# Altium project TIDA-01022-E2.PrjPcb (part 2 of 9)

## Sheet TIDA-01022-E2_ADC ANALOG INP CH3.SchDoc: ADC12DJxx00_CH3
size 431 x 279 mm; Date: Not shown in title block; ApprovedBy: Not shown in title block; CheckedBy: Not shown in title block; Author: Not shown in title block; CompanyName: Not shown in title block; DrawnBy: Avinash N; Engineer: Not shown in title block; Organization: Not shown in title block; Address1: Not shown in title block; Address2: Not shown in title block; Address3: Not shown in title block; Address4: Not shown in title block; DocumentNumber: 1; Revision: Use project parameter SCH_Rev; SheetNumber: 4; SheetTotal: 26; PageSetup: Record=PageOptions¦CenterHorizontal=True¦CenterVertical=True¦PrintScale=1.00¦XCorrection=1.00¦YCorrection=1.00¦PrintKind=0¦BorderSize=5000000¦LeftOffset=0¦BottomOffset=0¦Orientation=2¦PaperLength=1000¦PaperWidth=1000¦Scale=100¦PaperSource=15¦PrintQuality=600¦MediaType=1¦DitherType=10¦PaperKind=Letter¦PrintScaleMode=1
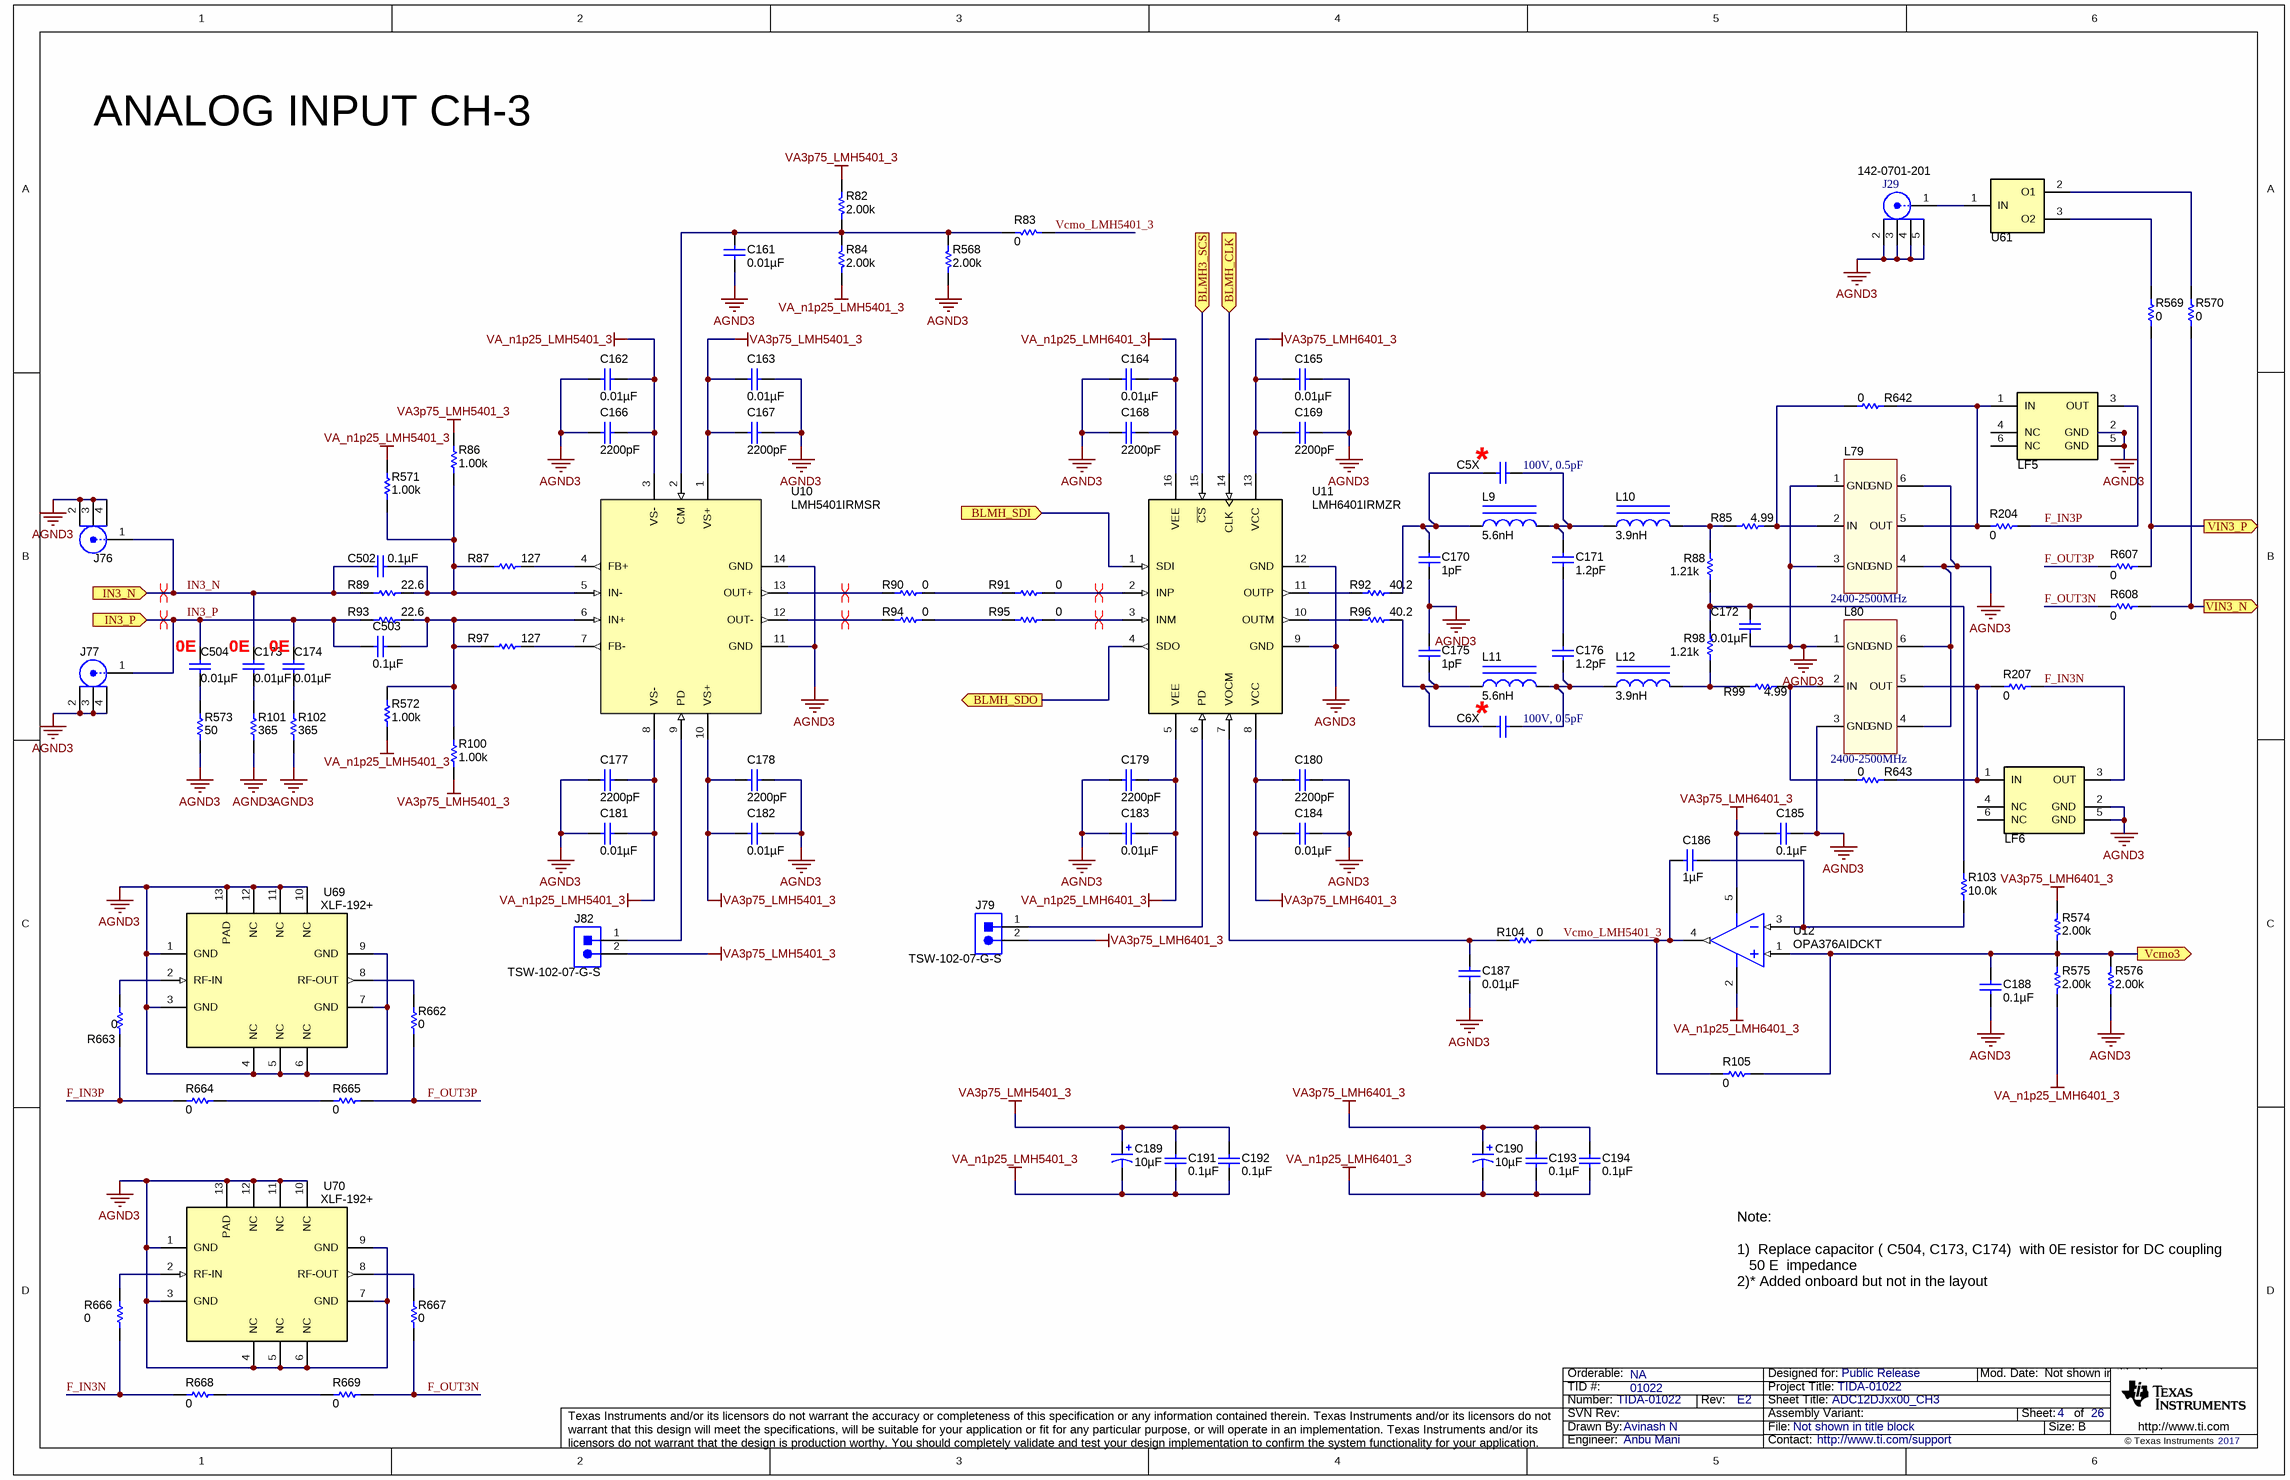
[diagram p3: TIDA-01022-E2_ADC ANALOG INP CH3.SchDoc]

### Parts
C5X  100V, 0.5pF  [0603_1.6x0.8x0.8mm_Reflow Soldering]
C6X  100V, 0.5pF  [0603_1.6x0.8x0.8mm_Reflow Soldering]
C161  ValueDisplayed: 0.01µF  [0402]  (hidden comment: GRM155R71E103KA01D)
C162  ValueDisplayed: 0.01µF  [0306]  (hidden comment: LLL185R71E103MA01L)
C163  ValueDisplayed: 0.01µF  [0306]  (hidden comment: LLL185R71E103MA01L)
C164  ValueDisplayed: 0.01µF  [0306]  (hidden comment: LLL185R71E103MA01L)
C165  ValueDisplayed: 0.01µF  [0306]  (hidden comment: LLL185R71E103MA01L)
C166  ValueDisplayed: 2200pF  [0306]  (hidden comment: LLL185R71H222MA01L)
C167  ValueDisplayed: 2200pF  [0306]  (hidden comment: LLL185R71H222MA01L)
C168  ValueDisplayed: 2200pF  [0306]  (hidden comment: LLL185R71H222MA01L)
C169  ValueDisplayed: 2200pF  [0306]  (hidden comment: LLL185R71H222MA01L)
C170  ValueDisplayed: 1pF  [0402]  (hidden comment: GRM1555C1H1R0CA01D)
C171  ValueDisplayed: 1.2pF  [0402]  (hidden comment: GRM1555C1H1R2BA01D)
C172  ValueDisplayed: 0.01µF  [0402]  (hidden comment: GRM155R71E103KA01D)
C173  ValueDisplayed: 0.01µF  [0402]  (hidden comment: GRM155R71E103KA01D)
C174  ValueDisplayed: 0.01µF  [0402]  (hidden comment: GRM155R71E103KA01D)
C175  ValueDisplayed: 1pF  [0402]  (hidden comment: GRM1555C1H1R0CA01D)
C176  ValueDisplayed: 1.2pF  [0402]  (hidden comment: GRM1555C1H1R2BA01D)
C177  ValueDisplayed: 2200pF  [0306]  (hidden comment: LLL185R71H222MA01L)
C178  ValueDisplayed: 2200pF  [0306]  (hidden comment: LLL185R71H222MA01L)
C179  ValueDisplayed: 2200pF  [0306]  (hidden comment: LLL185R71H222MA01L)
C180  ValueDisplayed: 2200pF  [0306]  (hidden comment: LLL185R71H222MA01L)
C181  ValueDisplayed: 0.01µF  [0306]  (hidden comment: LLL185R71E103MA01L)
C182  ValueDisplayed: 0.01µF  [0306]  (hidden comment: LLL185R71E103MA01L)
C183  ValueDisplayed: 0.01µF  [0306]  (hidden comment: LLL185R71E103MA01L)
C184  ValueDisplayed: 0.01µF  [0306]  (hidden comment: LLL185R71E103MA01L)
C185  ValueDisplayed: 0.1µF  [0402]  (hidden comment: C1005X5R1A104K050BA)
C186  ValueDisplayed: 1µF  [0603]  (hidden comment: C1608X5R1A105K080AC)
C187  ValueDisplayed: 0.01µF  [0402]  (hidden comment: GRM155R71E103KA01D)
C188  ValueDisplayed: 0.1µF  [0402]  (hidden comment: C1005X5R1A104K050BA)
C189  ValueDisplayed: 10µF  [3216-18]  (hidden comment: TPSA106K010R0900)
C190  ValueDisplayed: 10µF  [3216-18]  (hidden comment: TPSA106K010R0900)
C191  ValueDisplayed: 0.1µF  [0402]  (hidden comment: C1005X5R1A104K050BA)
C192  ValueDisplayed: 0.1µF  [0402]  (hidden comment: C1005X5R1A104K050BA)
C193  ValueDisplayed: 0.1µF  [0402]  (hidden comment: C1005X5R1A104K050BA)
C194  ValueDisplayed: 0.1µF  [0402]  (hidden comment: C1005X5R1A104K050BA)
C502  ValueDisplayed: 0.1µF  [0402]  (hidden comment: GRM155R71C104JA88D)
C503  ValueDisplayed: 0.1µF  [0402]  (hidden comment: GRM155R71C104JA88D)
C504  ValueDisplayed: 0.01µF  [0402]  (hidden comment: GRM155R71E103KA01D)
J29  142-0701-201  [Johnson_142-0701-20x]
J76  142-0771-831  [Johnson_142-0771-831]  (value not drawn)
J77  142-0771-831  [Johnson_142-0771-831]  (value not drawn)
J79  TSW-102-07-G-S  [TSW-102-07-G-S]
J82  TSW-102-07-G-S  [TSW-102-07-G-S]
L9  ValueDisplayed: 5.6nH  [LQW18A]  (hidden comment: LQW18AN5N6D10D)
L10  ValueDisplayed: 3.9nH  [0603HC]  (hidden comment: 0603HC-3N9XJLU)
L11  ValueDisplayed: 5.6nH  [LQW18A]  (hidden comment: LQW18AN5N6D10D)
L12  ValueDisplayed: 3.9nH  [0603HC]  (hidden comment: 0603HC-3N9XJLU)
L79  value 2400-2500MHz  [WE-LPF_0603]  (hidden comment: WE-LPF, 748112024)
L80  value 2400-2500MHz  [WE-LPF_0603]  (hidden comment: WE-LPF, 748112024)
LF5  LFL182G45TC3B746  [FIL_LFL18_TC1]  (value not drawn)
LF6  LFL182G45TC3B746  [FIL_LFL18_TC1]  (value not drawn)
R82  ValueDisplayed: 2.00k  [0402]  (hidden comment: CRCW04022K00FKED)
R83  ValueDisplayed: 0  [0402]  (hidden comment: CRCW04020000Z0ED)
R84  ValueDisplayed: 2.00k  [0402]  (hidden comment: CRCW04022K00FKED)
R85  ValueDisplayed: 4.99  [0402]  (hidden comment: CRCW04024R99FKED)
R86  ValueDisplayed: 1.00k  [0402]  (hidden comment: ERJ-2RKF1001X)
R87  ValueDisplayed: 127  [0402]  (hidden comment: CRCW0402127RFKED)
R88  ValueDisplayed: 1.21k  [0402]  (hidden comment: CRCW04021K21FKED)
R89  ValueDisplayed: 22.6  [0402]  (hidden comment: CRCW040222R6FKED)
R90  ValueDisplayed: 0  [0402]  (hidden comment: CRCW04020000Z0ED)
R91  ValueDisplayed: 0  [0402]  (hidden comment: CRCW04020000Z0ED)
R92  ValueDisplayed: 40.2  [0402]  (hidden comment: CRCW040240R2FKED)
R93  ValueDisplayed: 22.6  [0402]  (hidden comment: CRCW040222R6FKED)
R94  ValueDisplayed: 0  [0402]  (hidden comment: CRCW04020000Z0ED)
R95  ValueDisplayed: 0  [0402]  (hidden comment: CRCW04020000Z0ED)
R96  ValueDisplayed: 40.2  [0402]  (hidden comment: CRCW040240R2FKED)
R97  ValueDisplayed: 127  [0402]  (hidden comment: CRCW0402127RFKED)
R98  ValueDisplayed: 1.21k  [0402]  (hidden comment: CRCW04021K21FKED)
R99  ValueDisplayed: 4.99  [0402]  (hidden comment: CRCW04024R99FKED)
R100  ValueDisplayed: 1.00k  [0402]  (hidden comment: ERJ-2RKF1001X)
R101  ValueDisplayed: 365  [0402]  (hidden comment: CRCW0402365RFKED)
R102  ValueDisplayed: 365  [0402]  (hidden comment: CRCW0402365RFKED)
R103  ValueDisplayed: 10.0k  [0402]  (hidden comment: CRCW040210K0FKED)
R104  ValueDisplayed: 0  [0402]  (hidden comment: CRCW04020000Z0ED)
R105  ValueDisplayed: 0  [0402]  (hidden comment: CRCW04020000Z0ED)
R204  ValueDisplayed: 0  [0402_FILTER]  (hidden comment: CRCW04020000Z0ED)
R207  ValueDisplayed: 0  [0402_FILTER]  (hidden comment: CRCW04020000Z0ED)
R568  ValueDisplayed: 2.00k  [0402]  (hidden comment: CRCW04022K00FKED)
R569  ValueDisplayed: 0  [0201_adc]  (hidden comment: CRCW02010000Z0ED)
R570  ValueDisplayed: 0  [0201_adc]  (hidden comment: CRCW02010000Z0ED)
R571  ValueDisplayed: 1.00k  [0402]  (hidden comment: ERJ-2RKF1001X)
R572  ValueDisplayed: 1.00k  [0402]  (hidden comment: ERJ-2RKF1001X)
R573  ValueDisplayed: 50  [0402]  (hidden comment: FC0402E50R0BTBST1)
R574  ValueDisplayed: 2.00k  [0402]  (hidden comment: CRCW04022K00FKED)
R575  ValueDisplayed: 2.00k  [0402]  (hidden comment: CRCW04022K00FKED)
R576  ValueDisplayed: 2.00k  [0402]  (hidden comment: CRCW04022K00FKED)
R607  ValueDisplayed: 0  [0201_adc]  (hidden comment: CRCW02010000Z0ED)
R608  ValueDisplayed: 0  [0201_adc]  (hidden comment: CRCW02010000Z0ED)
R642  ValueDisplayed: 0  [0402_FILTER]  (hidden comment: CRCW04020000Z0ED)
R643  ValueDisplayed: 0  [0402_FILTER]  (hidden comment: CRCW04020000Z0ED)
R662  ValueDisplayed: 0  [0201_adc]  (hidden comment: CRCW02010000Z0ED)
R663  ValueDisplayed: 0  [0201_adc]  (hidden comment: CRCW02010000Z0ED)
R664  ValueDisplayed: 0  [0201_adc]  (hidden comment: CRCW02010000Z0ED)
R665  ValueDisplayed: 0  [0201_adc]  (hidden comment: CRCW02010000Z0ED)
R666  ValueDisplayed: 0  [0201_adc]  (hidden comment: CRCW02010000Z0ED)
R667  ValueDisplayed: 0  [0201_adc]  (hidden comment: CRCW02010000Z0ED)
R668  ValueDisplayed: 0  [0201_adc]  (hidden comment: CRCW02010000Z0ED)
R669  ValueDisplayed: 0  [0201_adc]  (hidden comment: CRCW02010000Z0ED)
U10  LMH5401IRMSR  [RMS0014A]
U11  LMH6401IRMZR  [RMZ0016A]
U12  OPA376AIDCKT  [DCK0005A_N]
U61  BAL-0006SMG  [Marki_BAL-0006SMG]  (value not drawn)
U69  XLF-192+  [DQ1225]
U70  XLF-192+  [DQ1225]

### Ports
BLMH3_SCS (in), BLMH_CLK (in), BLMH_SDI (in), BLMH_SDO (out), IN3_N (in), IN3_P (in), Vcmo3 (out), VIN3_N (out), VIN3_P (out)

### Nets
AGND3: C161.2 C162.1 C163.1 C164.1 C165.1 C166.2 C167.2 C168.2 C169.2 C170.2 C172.2 C175.2 C177.2 C178.2 C179.2 C180.2 C181.1 C182.1 C183.1 C184.1 C185.1 C187.2 C188.2 J29.2 J29.3 J29.4 J29.5 J76.2 J76.3 J76.4 J77.2 J77.3 J77.4 L79.1(GND) L79.3(GND) L79.4(GND) L79.6(GND) L80.1(GND) L80.3(GND) L80.4(GND) L80.6(GND) LF5.2(GND) LF5.5(GND) LF6.2(GND) LF6.5(GND) R101.1 R102.1 R568.1 R573.1 R576.1 U10.11(GND) U10.14(GND) U11.9(GND) U11.12(GND) U69.1(GND) U69.3(GND) U69.4(NC) U69.5(NC) U69.6(NC) U69.7(GND) U69.9(GND) U69.10(NC) U69.11(NC) U69.12(NC) U69.13(PAD) U70.1(GND) U70.3(GND) U70.4(NC) U70.5(NC) U70.6(NC) U70.7(GND) U70.9(GND) U70.10(NC) U70.11(NC) U70.12(NC) U70.13(PAD)  [project net AGND]
VA3p75_LMH5401_3: C163.2 C167.1 C178.1 C182.2 C189.1(+) C191.1 C192.1 J82.2 R82.2 R86.2 R100.1 U10.1(VS+) U10.10(VS+)
VA3p75_LMH6401_3: C165.2 C169.1 C180.1 C184.2 C185.2 C190.1(+) C193.1 C194.1 J79.2 R574.2 U11.8(VCC) U11.13(VCC) U12.5(V+)
VA_n1p25_LMH5401_3: C162.2 C166.1 C177.1 C181.2 C189.2(-) C191.2 C192.2 R84.1 R571.2 R572.2 U10.3(VS-) U10.8(VS-)
VA_n1p25_LMH6401_3: C164.2 C168.1 C179.1 C183.2 C190.2(-) C193.2 C194.2 R575.1 U11.5(VEE) U11.16(VEE) U12.2(V-)
BLMH3_SCS: U11.15(~{CS}) ; port BLMH3_SCS
BLMH_CLK: U11.14(CLK) ; port BLMH_CLK
BLMH_SDI: U11.1(SDI) ; port BLMH_SDI
BLMH_SDO: U11.4(SDO) ; port BLMH_SDO
F_IN3N: LF6.3(OUT) R207.2 R666.1 R668.1
F_IN3P: LF5.3(OUT) R204.2 R663.1 R664.1
F_OUT3N: R608.1 R667.1 R669.2
F_OUT3P: R607.1 R662.1 R665.2
IN3_N: C173.1 C502.2 J76.1 R89.1 ; port IN3_N
IN3_P: C174.1 C503.1 C504.1 J77.1 R93.1 ; port IN3_P
Vcmo3: C188.1 R105.1 R574.1 R575.2 R576.2 U12.1(IN+) ; port Vcmo3
Vcmo_LMH5401_3: C186.1 R83.2 R104.1 R105.2 U12.4(OUT)
VIN3_N: R570.2 R608.2 ; port VIN3_N
VIN3_P: R569.2 R607.2 ; port VIN3_P
NetC5X_1: C5X.1 C170.1 L9.1 R92.1
NetC5X_2: C5X.2 C171.1 L9.2 L10.1
NetC6X_1: C6X.1 C175.1 L11.1 R96.1
NetC6X_2: C6X.2 C176.1 L11.2 L12.1
NetC161_1: C161.1 R82.1 R83.1 R84.2 R568.2 U10.2(CM)
NetC171_2: C171.2 C176.2
NetC172_1: C172.1 R88.1 R98.1 R103.2
NetC173_2: C173.2 R101.2
NetC174_2: C174.2 R102.2
NetC186_2: C186.2 R103.1 U12.3(IN-)
NetC187_1: C187.1 R104.2 U11.7(VOCM)
NetC502_1: C502.1 R86.1 R87.1 R89.2 R571.1 U10.5(IN-)
NetC503_2: C503.2 R93.2 R97.1 R100.2 R572.1 U10.6(IN+)
NetC504_2: C504.2 R573.2
NetJ29_1: J29.1 U61.1(IN)
NetJ79_1: J79.1 U11.6(PD)
NetJ82_1: J82.1 U10.9(PD)
NetL10_2: L10.2 R85.1 R88.2
NetL12_2: L12.2 R98.2 R99.1
NetL79_2: L79.2(IN) R85.2 R642.1
NetL79_5: L79.5(OUT) LF5.1(IN) R204.1 R642.2
NetL80_2: L80.2(IN) R99.2 R643.1
NetL80_5: L80.5(OUT) LF6.1(IN) R207.1 R643.2
NetR87_2: R87.2 U10.4(FB+)
NetR90_1: R90.1 U10.13(OUT+)
NetR90_2: R90.2 R91.2
NetR91_1: R91.1 U11.2(INP)
NetR92_2: R92.2 U11.11(OUTP)
NetR94_1: R94.1 U10.12(OUT-)
NetR94_2: R94.2 R95.2
NetR95_1: R95.1 U11.3(INM)
NetR96_2: R96.2 U11.10(OUTM)
NetR97_2: R97.2 U10.7(FB-)
NetR569_1: R569.1 U61.3(O2)
NetR570_1: R570.1 U61.2(O1)
NetR662_2: R662.2 U69.8(RF-OUT)
NetR663_2: R663.2 U69.2(RF-IN)
NetR664_2: R664.2 R665.1
NetR666_2: R666.2 U70.2(RF-IN)
NetR667_2: R667.2 U70.8(RF-OUT)
NetR668_2: R668.2 R669.1

Not connected (* = marked no-connect by the designer): LF5 4(NC) 6(NC); LF6 4(NC) 6(NC)

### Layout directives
differential pair: IN3_N, IN3_P, NetR90_1, NetR91_1, NetR94_1, NetR95_1

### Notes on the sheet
- ANALOG INPUT CH-3
- (near C5X) *
- (near C504) 0E
- (near C173) 0E
- (near C174) 0E
- *
- Note:
  1)  Replace capacitor ( C504, C173, C174)  with 0E resistor for DC coupling
  50 E  impedance
  2)* Added onboard but not in the layout

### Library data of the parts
C5X C6X = 885012006086: WCAP-CSGP Ceramic Capacitors, 0603, NP0, 100V, 0.5pF; Rated Voltage: 100V DC
C161 C172-C174 C187 C504 = GRM155R71E103KA01D: CAP, CERM, 0.01 µF, 25 V, +/- 10%, X7R, 0402; Manufacturer: MuRata; Polarized: N; CompType: Capacitor; Value: 0.01uF; U/M: EA; Cap_F: 0.00000001; Tolerance_%: 10; Value1: Unknown; VDC_V: 25; Value2: 25V; TaMin_C: -55; TaMax_C: 125; SizeArea_mm2: 0.5; SizeAreaWB_mm2: 3; SizeX_mm: 1; SizeZ_mm: 0.6; AEC Category: Q200
C162-C165 C181-C184 = LLL185R71E103MA01L: CAP, CERM, 0.01 µF, 25 V, +/- 20%, X7R, 0306; Manufacturer: MuRata; Polarized: N; CompType: Capacitor; Value: 0.01uF; U/M: EA; Cap_F: 0.00000001; Tolerance_%: 20; Value1: Unknown; VDC_V: 25; Value2: 25V; TaMin_C: -55; TaMax_C: 125; SizeArea_mm2: 1.28; SizeAreaWB_mm2: 4.68; SizeX_mm: 0.8; SizeY_mm: 1.6; SizeZ_mm: 0.6; AEC Category: Q200
C166-C169 C177-C180 = LLL185R71H222MA01L: CAP, CERM, 2200 pF, 50 V, +/- 20%, X7R, 0306; Manufacturer: MuRata; Polarized: N; CompType: Capacitor; Value: 2200pF; U/M: EA; Cap_F: 0.0000000022; Tolerance_%: 20; Value1: Unknown; VDC_V: 50; Value2: 50V; TaMin_C: -55; TaMax_C: 125; SizeArea_mm2: 1.28; SizeAreaWB_mm2: 4.68; SizeX_mm: 0.8; SizeY_mm: 1.6; SizeZ_mm: 0.6; AEC Category: Q200
C170 C175 = GRM1555C1H1R0CA01D: CAP, CERM, 1 pF, 50 V, +/- 5%, C0G/NP0, 0402; Manufacturer: MuRata; Polarized: N; CompType: Capacitor; Value: 1pF; U/M: EA; Cap_F: 0.000000000001; Tolerance_%: 5; Value1: Unknown; VDC_V: 50; Value2: 50V; TaMin_C: -55; TaMax_C: 125; SizeArea_mm2: 0.5; SizeAreaWB_mm2: 3; SizeX_mm: 1; SizeZ_mm: 0.6; AEC Category: Q200
C171 C176 = GRM1555C1H1R2BA01D: CAP, CERM, 1.2 pF, 50 V, +/- 8.3%, C0G/NP0, 0402; Manufacturer: MuRata; Polarized: N; CompType: Capacitor; Value: 1.2pF; U/M: EA; Cap_F: 0.0000000000012; Tolerance_%: 8.3; Value1: Unknown; VDC_V: 50; Value2: 50V; TaMin_C: -55; TaMax_C: 125; SizeArea_mm2: 0.5; SizeAreaWB_mm2: 3; SizeX_mm: 1; SizeZ_mm: 0.6; AEC Category: Q200
C185 C188 C191-C194 = C1005X5R1A104K050BA: CAP, CERM, 0.1 µF, 10 V, +/- 10%, X5R, 0402; Manufacturer: TDK; Polarized: N; CompType: Capacitor; Value: 0.1uF; U/M: EA; Cap_F: 0.0000001; Tolerance_%: 10; Value1: Unknown; Value2: 10V; TaMin_C: -55; TaMax_C: 85; SizeArea_mm2: 0.5; SizeAreaWB_mm2: 3; SizeX_mm: 1; SizeZ_mm: 0.6; AEC Category: Q200
C186 = C1608X5R1A105K080AC: CAP, CERM, 1 µF, 10 V, +/- 10%, X5R, 0603; Manufacturer: TDK; Polarized: N; CompType: Capacitor; Value: 1uF; U/M: EA; Cap_F: 0.000001; Tolerance_%: 10; Value1: Unknown; Value2: 10V; TaMin_C: -55; TaMax_C: 85; SizeArea_mm2: 1.28; SizeAreaWB_mm2: 4.68; SizeX_mm: 1.6; SizeY_mm: 0.8; SizeZ_mm: 1; AEC Category: Q200
C189 C190 = TPSA106K010R0900: CAP, TA, 10 µF, 10 V, +/- 10%, 0.9 ohm, SMD; Manufacturer: AVX; Polarized: Y; CompType: Capacitor; Value: 10uF; U/M: EA; Cap_F: 0.00001; Tolerance_%: 10; Value1: 0.9 ohm; Value2: 10V; ESR_ohm: 0.9; IRMS_A: 0.26; TaMin_C: -55; TaMax_C: 125; Cap_Case: A; SizeAreaWB_mm2: 10.92; SizeArea_mm2: 5.12; SizeX_mm: 3.2; SizeY_mm: 1.6; SizeZ_mm: 1.8; AEC Category: Q200
C502 C503 = GRM155R71C104JA88D: CAP, CERM, 0.1 µF, 16 V, +/- 5%, X7R, 0402; Manufacturer: MuRata; Polarized: N; CompType: Capacitor; Value: 0.1uF; U/M: EA; Cap_F: 0.0000001; Tolerance_%: 5; Value1: Unknown; VDC_V: 16; Value2: 16V; TaMin_C: -55; TaMax_C: 125; SizeArea_mm2: 0.5; SizeAreaWB_mm2: 3; SizeX_mm: 1; SizeZ_mm: 0.6; AEC Category: Q200
J29 = 142-0701-201: Connector, TH, SMA; Manufacturer: Emerson Network Power; SymbolCreator: X0208326
J76 J77 = 142-0771-831: JACK, SMA, 50 Ohm, Gold, Edge Mount; Manufacturer: Johnson; SymbolCreator: Altium; Gender: Female; Voltage_V: 170
J79 J82 = TSW-102-07-G-S: Header, 100mil, 2x1, Gold, TH; Manufacturer: Samtec; SymbolCreator: a0412235; Pitch_mm: 2.54; Gender: Male; Shrouded: N; Row_Count: 1; Current_A: 6.3; Voltage_V: 550; Cert_CSA: Y
L9 L11 = LQW18AN5N6D10D: Inductor, Wirewound, 5.6 nH, 0.9 A, 0.045 ohm, SMD; Manufacturer: MuRata; Value: 5.6nH; Ind_H: 5.6E-9; Imax_A: 0.9; Irms: 0.9A @ C rise; DCR_ohm: 0.045; Value2: 0.9A; SizeAreaWB_mm2: 4.68; SizeArea_mm2: 1.28; SizeX_mm: 1.6; SizeY_mm: 0.8; SizeZ_mm: 1; AEC Category: Q200; AEC Qualified: N
L10 L12 = 0603HC-3N9XJLU: Inductor, Wirewound, Ceramic, 3.9 nH, 2.2 A, 0.054 ohm, SMD; Manufacturer: Coilcraft; Value: 3.9nH; Ind_H: 3.9E-9; Imax_A: 2.2; Irms: 2.4A @ 20C rise; DCR_ohm: 0.054; Value2: 2.2A; SizeAreaWB_mm2: 5.936; SizeArea_mm2: 2.016; SizeX_mm: 1.8; SizeY_mm: 1.12; SizeZ_mm: 1.02; AEC Category: Q200
L79 L80 = WE-LPF, 748112024: WE-LPF Multilayer Chip Low-Pass Filter, size 0603, 2400-2500MHz
LF5 LF6 = LFL182G45TC3B746: Filter for Communication Equipment, SMD; Manufacturer: MuRata; SymbolCreator: Altium; SizeAreaWB_mm2: 4.68; SizeArea_mm2: 1.28; SizeX_mm: 1.6; SizeY_mm: 0.8; SizeZ_mm: 0.7
R82 R84 R568 R574-R576 = CRCW04022K00FKED: RES, 2.00 k, 1%, 0.063 W, 0402; Manufacturer: Vishay-Dale; CompType: Resistor; Value: 2.00k; Res_ohm: 2000; Value_Code: 2k00; Tolerance_%: 1; Power_W: 0.063; Value2: 0.063W; VDC_V: 50; TempCo: 100 ppm/C; SizeArea_mm2: 0.5; SizeZ_mm: 0.6; EIA_Code: E96; U/M: EA; AEC Category: Q200
R83 R90 R91 R94 R95 R104 R105 R204 R207 R642 R643 = CRCW04020000Z0ED: RES, 0, 5%, 0.063 W, 0402; Manufacturer: Vishay-Dale; CompType: Resistor; Value: 0; Value_Code: 0000; Tolerance_%: 5; Power_W: 0.063; Value2: 0.063W; VDC_V: 50; TempCo: 200 ppm/C; SizeArea_mm2: 0.5; SizeX_mm: 1; SizeZ_mm: 0.6; EIA_Code: E24; U/M: EA; AEC Category: Q200
R85 R99 = CRCW04024R99FKED: RES, 4.99, 1%, 0.063 W, 0402; Manufacturer: Vishay-Dale; CompType: Resistor; Value: 4.99; Value_Code: 4R99; Tolerance_%: 1; Power_W: 0.063; Value2: 0.063W; VDC_V: 50; TempCo: 100 ppm/C; SizeArea_mm2: 0.5; SizeZ_mm: 0.6; EIA_Code: E96; U/M: EA; AEC Category: Q200
R86 R100 R571 R572 = ERJ-2RKF1001X: RES, 1.00 k, 1%, 0.1 W, 0402; Manufacturer: Panasonic; CompType: Resistor; Value: 1.00k; Res_ohm: 1000; Value_Code: 1k00; Tolerance_%: 1; Power_W: 0.1; Value2: 0.1W; VDC_V: 50; TempCo: 100 ppm/C; SizeArea_mm2: 0.5; SizeZ_mm: 0.6; EIA_Code: E96; U/M: EA; AEC Category: Q200
R87 R97 = CRCW0402127RFKED: RES, 127, 1%, 0.063 W, 0402; Manufacturer: Vishay-Dale; CompType: Resistor; Value: 127; Value_Code: 127R; Tolerance_%: 1; Power_W: 0.063; Value2: 0.063W; VDC_V: 50; TempCo: 100 ppm/C; SizeArea_mm2: 0.5; SizeZ_mm: 0.6; EIA_Code: E96; U/M: EA; AEC Category: Q200
R88 R98 = CRCW04021K21FKED: RES, 1.21 k, 1%, 0.063 W, 0402; Manufacturer: Vishay-Dale; CompType: Resistor; Value: 1.21k; Res_ohm: 1210; Value_Code: 1k21; Tolerance_%: 1; Power_W: 0.063; Value2: 0.063W; VDC_V: 50; TempCo: 100 ppm/C; SizeArea_mm2: 0.5; SizeZ_mm: 0.6; EIA_Code: E96; U/M: EA; AEC Category: Q200
R89 R93 = CRCW040222R6FKED: RES, 22.6, 1%, 0.063 W, 0402; Manufacturer: Vishay-Dale; CompType: Resistor; Value: 22.6; Value_Code: 22R6; Tolerance_%: 1; Power_W: 0.063; Value2: 0.063W; VDC_V: 50; TempCo: 100 ppm/C; SizeArea_mm2: 0.5; SizeZ_mm: 0.6; EIA_Code: E96; U/M: EA; AEC Category: Q200
R92 R96 = CRCW040240R2FKED: RES, 40.2, 1%, 0.063 W, 0402; Manufacturer: Vishay-Dale; CompType: Resistor; Value: 40.2; Value_Code: 40R2; Tolerance_%: 1; Power_W: 0.063; Value2: 0.063W; VDC_V: 50; TempCo: 100 ppm/C; SizeArea_mm2: 0.5; SizeZ_mm: 0.6; EIA_Code: E96; U/M: EA; AEC Category: Q200
R101 R102 = CRCW0402365RFKED: RES, 365, 1%, 0.063 W, 0402; Manufacturer: Vishay-Dale; CompType: Resistor; Value: 365; Value_Code: 365R; Tolerance_%: 1; Power_W: 0.063; Value2: 0.063W; VDC_V: 50; TempCo: 100 ppm/C; SizeArea_mm2: 0.5; SizeZ_mm: 0.6; EIA_Code: E96; U/M: EA; AEC Category: Q200
R103 = CRCW040210K0FKED: RES, 10.0 k, 1%, 0.063 W, 0402; Manufacturer: Vishay-Dale; CompType: Resistor; Value: 10.0k; Res_ohm: 10000; Value_Code: 10k0; Tolerance_%: 1; Power_W: 0.063; Value2: 0.063W; VDC_V: 50; TempCo: 100 ppm/C; SizeArea_mm2: 0.5; SizeZ_mm: 0.6; EIA_Code: E96; U/M: EA; AEC Category: Q200
R569 R570 R607 R608 R662-R669 = CRCW02010000Z0ED: RES, 0, 5%, 0.05 W, 0201; Manufacturer: Vishay-Dale; CompType: Resistor; Value: 0; Value_Code: 0000; Tolerance_%: 5; Power_W: 0.05; Value2: 0.05W; TempCo: ppm/C; SizeArea_mm2: 0.18; SizeX_mm: 0.6; SizeY_mm: 0.3; SizeZ_mm: 0.26; EIA_Code: E24; U/M: EA; AEC Category: Q200; AEC Qualified: N
R573 = FC0402E50R0BTBST1: RES, 50, 0.1%, 0.5 W, 0402; Manufacturer: Vishay Thin Film; CompType: Resistor; Value: 50; Value_Code: 50R0; Tolerance_%: 0.1; Power_W: 0.5; Value2: 0.5W; TempCo: 0.1 ppm/C; SizeX_mm: 1; SizeZ_mm: 0.6; U/M: EA; AEC Category: Q200; AEC Qualified: N
U10 = LMH5401IRMSR: 8GHz Ultra Wideband Fully Differential Amplifier, RMS0014A (UQFN-14); Alternate PartNumber: LMH5401IRMST; Manufacturer: Texas Instruments; SymbolCreator: Altium; SizeArea_mm2: 6.25; SizeAreaWB_mm2: 12.25; SizeX_mm: 2.5; SizeZ_mm: 0.6; CompType: IC; U/M: EA
U11 = LMH6401IRMZR: 4.5 GHz Ultra Wideband Digital Variable Gain Amplifier, RMZ0016A (UQFN-HR-16); Alternate PartNumber: LMH6401IRMZT; Manufacturer: Texas Instruments; SymbolCreator: Altium; SizeArea_mm2: 9; SizeAreaWB_mm2: 16; SizeX_mm: 3; SizeZ_mm: 0.65; CompType: IC; U/M: EA
U12 = OPA376AIDCKT: Precision, Low Noise, Low Iq Operational Amplifier, 2.2 to 5.5 V, -40 to 125 degC, 5-pin SOT23 (DCK0005A), Green (RoHS & no Sb/Br); Manufacturer: Texas Instruments; Alternate PartNumber: Equivalent; CMRR(Min)(dB): 76; IIB(Max)(pA): 10; Iq per channel(Max)(mA): 0.95; Number of Channels: 1; Offset Drift(Typ)(uV/C): 0.32; Slew Rate(Typ)(V/us): 2; Sub Family: Low Input Bias Current Amp (<=10pA), Low Noise Amp (<=10nV/rtHz), Low Offset Voltage Amplifier (<=500uV), Low Supply Voltage Amplifier (<=2.7V), Precision Amplifier; Total Supply Voltage(Max)(+5V is 5, +/-5V is 10): 5.5; Total Supply Voltage(Min)(+5V is 5, +/-5V is 10): 2.2; Vio (25C)(Max)(mV): 0.025; Vn at 1kHz(Typ)(nV/rtHz): 7.5
U61 = BAL-0006SMG: Broadband Balun, 500 kHz to 6 GHz; Manufacturer: Marki Microwave; SymbolCreator: Altium; SizeAreaWB_mm2: 102.6169; SizeArea_mm2: 66.0969; SizeX_mm: 8.13; SizeZ_mm: 3.94
U69 U70 = CMP-0077784-1: Reflectionless Low Pass Filter, SMD; Manufacturer: Minicircuits; SizeArea_mm2: 9; SizeAreaWB_mm2: 16; SizeY_mm: 3; SizeZ_mm: 0.89

## Sheet TIDA-01022-E2_ADC ANALOG INP CH4.SchDoc: ADC12DJxx00_CH4
size 431 x 279 mm; Date: Not shown in title block; ApprovedBy: Not shown in title block; CheckedBy: Not shown in title block; Author: Not shown in title block; CompanyName: Not shown in title block; DrawnBy: Avinash N; Engineer: Not shown in title block; Organization: Not shown in title block; Address1: Not shown in title block; Address2: Not shown in title block; Address3: Not shown in title block; Address4: Not shown in title block; DocumentNumber: 1; Revision: Use project parameter SCH_Rev; SheetNumber: 5; SheetTotal: 26; PageSetup: Record=PageOptions¦CenterHorizontal=True¦CenterVertical=True¦PrintScale=1.00¦XCorrection=1.00¦YCorrection=1.00¦PrintKind=0¦BorderSize=5000000¦LeftOffset=0¦BottomOffset=0¦Orientation=2¦PaperLength=1000¦PaperWidth=1000¦Scale=100¦PaperSource=15¦PrintQuality=600¦MediaType=1¦DitherType=10¦PaperKind=Letter¦PrintScaleMode=1
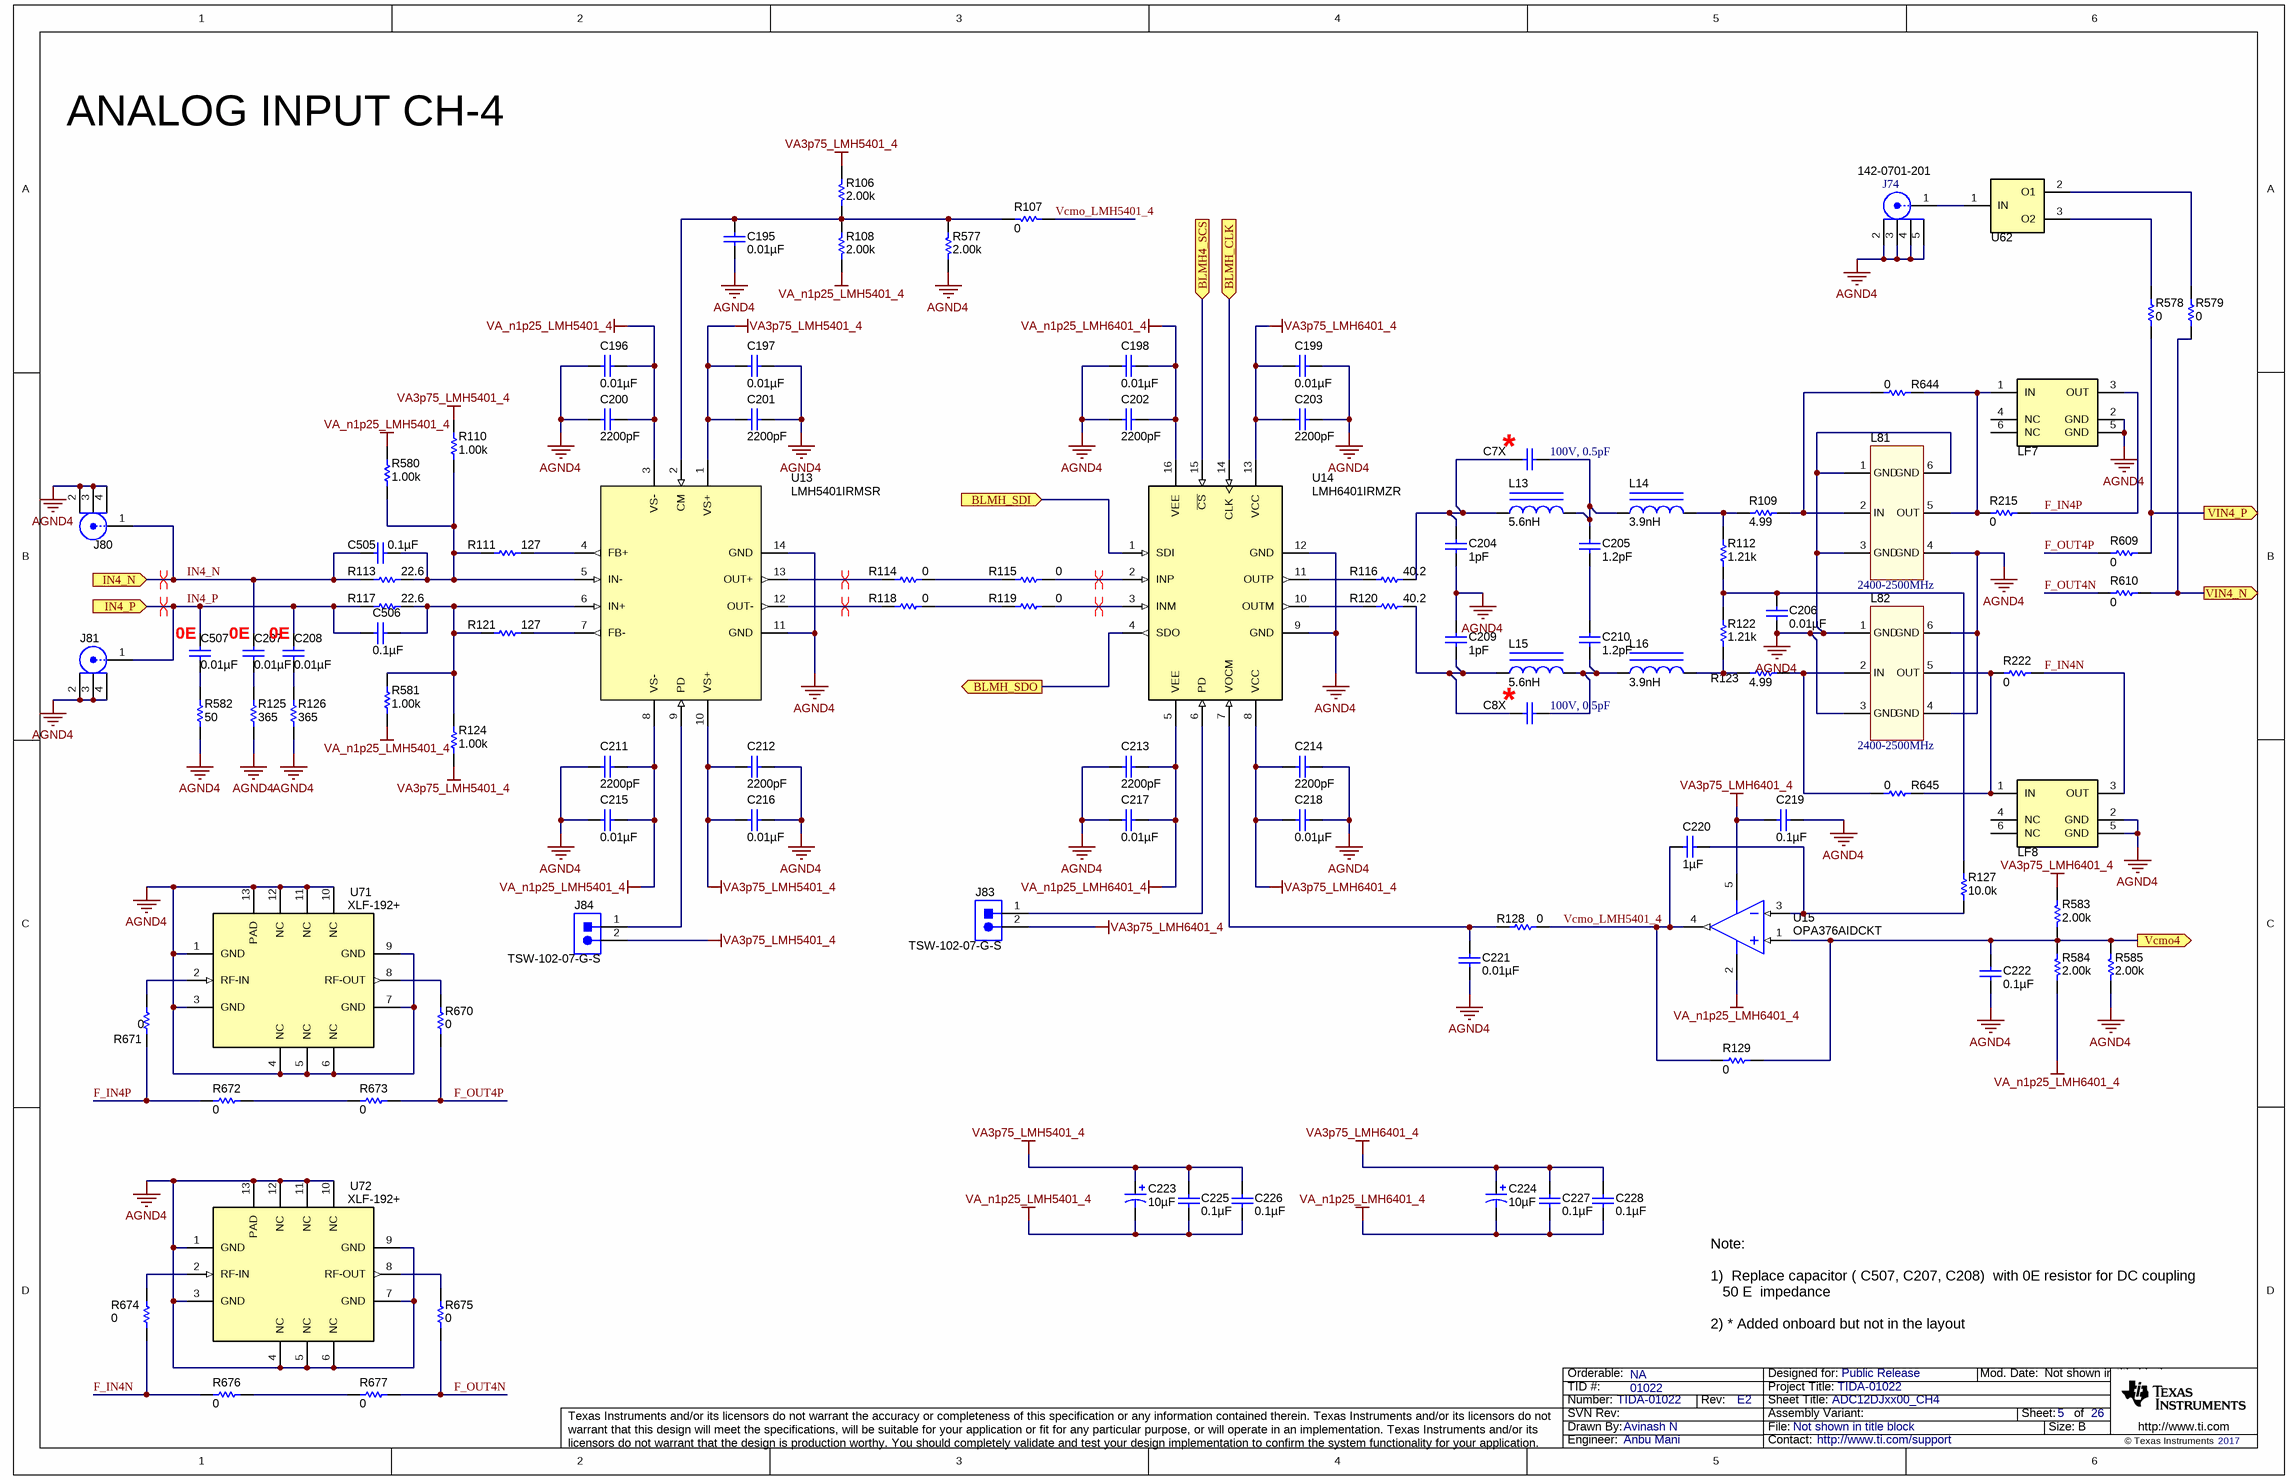
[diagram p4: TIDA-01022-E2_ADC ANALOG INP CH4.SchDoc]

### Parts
C7X  100V, 0.5pF  [0603_1.6x0.8x0.8mm_Reflow Soldering]
C8X  100V, 0.5pF  [0603_1.6x0.8x0.8mm_Reflow Soldering]
C195  ValueDisplayed: 0.01µF  [0402]  (hidden comment: GRM155R71E103KA01D)
C196  ValueDisplayed: 0.01µF  [0306]  (hidden comment: LLL185R71E103MA01L)
C197  ValueDisplayed: 0.01µF  [0306]  (hidden comment: LLL185R71E103MA01L)
C198  ValueDisplayed: 0.01µF  [0306]  (hidden comment: LLL185R71E103MA01L)
C199  ValueDisplayed: 0.01µF  [0306]  (hidden comment: LLL185R71E103MA01L)
C200  ValueDisplayed: 2200pF  [0306]  (hidden comment: LLL185R71H222MA01L)
C201  ValueDisplayed: 2200pF  [0306]  (hidden comment: LLL185R71H222MA01L)
C202  ValueDisplayed: 2200pF  [0306]  (hidden comment: LLL185R71H222MA01L)
C203  ValueDisplayed: 2200pF  [0306]  (hidden comment: LLL185R71H222MA01L)
C204  ValueDisplayed: 1pF  [0402]  (hidden comment: GRM1555C1H1R0CA01D)
C205  ValueDisplayed: 1.2pF  [0402]  (hidden comment: GRM1555C1H1R2BA01D)
C206  ValueDisplayed: 0.01µF  [0402]  (hidden comment: GRM155R71E103KA01D)
C207  ValueDisplayed: 0.01µF  [0402]  (hidden comment: GRM155R71E103KA01D)
C208  ValueDisplayed: 0.01µF  [0402]  (hidden comment: GRM155R71E103KA01D)
C209  ValueDisplayed: 1pF  [0402]  (hidden comment: GRM1555C1H1R0CA01D)
C210  ValueDisplayed: 1.2pF  [0402]  (hidden comment: GRM1555C1H1R2BA01D)
C211  ValueDisplayed: 2200pF  [0306]  (hidden comment: LLL185R71H222MA01L)
C212  ValueDisplayed: 2200pF  [0306]  (hidden comment: LLL185R71H222MA01L)
C213  ValueDisplayed: 2200pF  [0306]  (hidden comment: LLL185R71H222MA01L)
C214  ValueDisplayed: 2200pF  [0306]  (hidden comment: LLL185R71H222MA01L)
C215  ValueDisplayed: 0.01µF  [0306]  (hidden comment: LLL185R71E103MA01L)
C216  ValueDisplayed: 0.01µF  [0306]  (hidden comment: LLL185R71E103MA01L)
C217  ValueDisplayed: 0.01µF  [0306]  (hidden comment: LLL185R71E103MA01L)
C218  ValueDisplayed: 0.01µF  [0306]  (hidden comment: LLL185R71E103MA01L)
C219  ValueDisplayed: 0.1µF  [0402]  (hidden comment: C1005X5R1A104K050BA)
C220  ValueDisplayed: 1µF  [0603]  (hidden comment: C1608X5R1A105K080AC)
C221  ValueDisplayed: 0.01µF  [0402]  (hidden comment: GRM155R71E103KA01D)
C222  ValueDisplayed: 0.1µF  [0402]  (hidden comment: C1005X5R1A104K050BA)
C223  ValueDisplayed: 10µF  [3216-18]  (hidden comment: TPSA106K010R0900)
C224  ValueDisplayed: 10µF  [3216-18]  (hidden comment: TPSA106K010R0900)
C225  ValueDisplayed: 0.1µF  [0402]  (hidden comment: C1005X5R1A104K050BA)
C226  ValueDisplayed: 0.1µF  [0402]  (hidden comment: C1005X5R1A104K050BA)
C227  ValueDisplayed: 0.1µF  [0402]  (hidden comment: C1005X5R1A104K050BA)
C228  ValueDisplayed: 0.1µF  [0402]  (hidden comment: C1005X5R1A104K050BA)
C505  ValueDisplayed: 0.1µF  [0402]  (hidden comment: GRM155R71C104JA88D)
C506  ValueDisplayed: 0.1µF  [0402]  (hidden comment: GRM155R71C104JA88D)
C507  ValueDisplayed: 0.01µF  [0402]  (hidden comment: GRM155R71E103KA01D)
J74  142-0701-201  [Johnson_142-0701-20x]
J80  142-0771-831  [Johnson_142-0771-831]  (value not drawn)
J81  142-0771-831  [Johnson_142-0771-831]  (value not drawn)
J83  TSW-102-07-G-S  [TSW-102-07-G-S]
J84  TSW-102-07-G-S  [TSW-102-07-G-S]
L13  ValueDisplayed: 5.6nH  [LQW18A]  (hidden comment: LQW18AN5N6D10D)
L14  ValueDisplayed: 3.9nH  [0603HC]  (hidden comment: 0603HC-3N9XJLU)
L15  ValueDisplayed: 5.6nH  [LQW18A]  (hidden comment: LQW18AN5N6D10D)
L16  ValueDisplayed: 3.9nH  [0603HC]  (hidden comment: 0603HC-3N9XJLU)
L81  value 2400-2500MHz  [WE-LPF_0603]  (hidden comment: WE-LPF, 748112024)
L82  value 2400-2500MHz  [WE-LPF_0603]  (hidden comment: WE-LPF, 748112024)
LF7  LFL182G45TC3B746  [FIL_LFL18_TC1]  (value not drawn)
LF8  LFL182G45TC3B746  [FIL_LFL18_TC1]  (value not drawn)
R106  ValueDisplayed: 2.00k  [0402]  (hidden comment: CRCW04022K00FKED)
R107  ValueDisplayed: 0  [0402]  (hidden comment: CRCW04020000Z0ED)
R108  ValueDisplayed: 2.00k  [0402]  (hidden comment: CRCW04022K00FKED)
R109  ValueDisplayed: 4.99  [0402]  (hidden comment: CRCW04024R99FKED)
R110  ValueDisplayed: 1.00k  [0402]  (hidden comment: ERJ-2RKF1001X)
R111  ValueDisplayed: 127  [0402]  (hidden comment: CRCW0402127RFKED)
R112  ValueDisplayed: 1.21k  [0402]  (hidden comment: CRCW04021K21FKED)
R113  ValueDisplayed: 22.6  [0402]  (hidden comment: CRCW040222R6FKED)
R114  ValueDisplayed: 0  [0402]  (hidden comment: CRCW04020000Z0ED)
R115  ValueDisplayed: 0  [0402]  (hidden comment: CRCW04020000Z0ED)
R116  ValueDisplayed: 40.2  [0402]  (hidden comment: CRCW040240R2FKED)
R117  ValueDisplayed: 22.6  [0402]  (hidden comment: CRCW040222R6FKED)
R118  ValueDisplayed: 0  [0402]  (hidden comment: CRCW04020000Z0ED)
R119  ValueDisplayed: 0  [0402]  (hidden comment: CRCW04020000Z0ED)
R120  ValueDisplayed: 40.2  [0402]  (hidden comment: CRCW040240R2FKED)
R121  ValueDisplayed: 127  [0402]  (hidden comment: CRCW0402127RFKED)
R122  ValueDisplayed: 1.21k  [0402]  (hidden comment: CRCW04021K21FKED)
R123  ValueDisplayed: 4.99  [0402]  (hidden comment: CRCW04024R99FKED)
R124  ValueDisplayed: 1.00k  [0402]  (hidden comment: ERJ-2RKF1001X)
R125  ValueDisplayed: 365  [0402]  (hidden comment: CRCW0402365RFKED)
R126  ValueDisplayed: 365  [0402]  (hidden comment: CRCW0402365RFKED)
R127  ValueDisplayed: 10.0k  [0402]  (hidden comment: CRCW040210K0FKED)
R128  ValueDisplayed: 0  [0402]  (hidden comment: CRCW04020000Z0ED)
R129  ValueDisplayed: 0  [0402]  (hidden comment: CRCW04020000Z0ED)
R215  ValueDisplayed: 0  [0402_FILTER]  (hidden comment: CRCW04020000Z0ED)
R222  ValueDisplayed: 0  [0402_FILTER]  (hidden comment: CRCW04020000Z0ED)
R577  ValueDisplayed: 2.00k  [0402]  (hidden comment: CRCW04022K00FKED)
R578  ValueDisplayed: 0  [0201_adc]  (hidden comment: CRCW02010000Z0ED)
R579  ValueDisplayed: 0  [0201_adc]  (hidden comment: CRCW02010000Z0ED)
R580  ValueDisplayed: 1.00k  [0402]  (hidden comment: ERJ-2RKF1001X)
R581  ValueDisplayed: 1.00k  [0402]  (hidden comment: ERJ-2RKF1001X)
R582  ValueDisplayed: 50  [0402]  (hidden comment: FC0402E50R0BTBST1)
R583  ValueDisplayed: 2.00k  [0402]  (hidden comment: CRCW04022K00FKED)
R584  ValueDisplayed: 2.00k  [0402]  (hidden comment: CRCW04022K00FKED)
R585  ValueDisplayed: 2.00k  [0402]  (hidden comment: CRCW04022K00FKED)
R609  ValueDisplayed: 0  [0201_adc]  (hidden comment: CRCW02010000Z0ED)
R610  ValueDisplayed: 0  [0201_adc]  (hidden comment: CRCW02010000Z0ED)
R644  ValueDisplayed: 0  [0402_FILTER]  (hidden comment: CRCW04020000Z0ED)
R645  ValueDisplayed: 0  [0402_FILTER]  (hidden comment: CRCW04020000Z0ED)
R670  ValueDisplayed: 0  [0201_adc]  (hidden comment: CRCW02010000Z0ED)
R671  ValueDisplayed: 0  [0201_adc]  (hidden comment: CRCW02010000Z0ED)
R672  ValueDisplayed: 0  [0201_adc]  (hidden comment: CRCW02010000Z0ED)
R673  ValueDisplayed: 0  [0201_adc]  (hidden comment: CRCW02010000Z0ED)
R674  ValueDisplayed: 0  [0201_adc]  (hidden comment: CRCW02010000Z0ED)
R675  ValueDisplayed: 0  [0201_adc]  (hidden comment: CRCW02010000Z0ED)
R676  ValueDisplayed: 0  [0201_adc]  (hidden comment: CRCW02010000Z0ED)
R677  ValueDisplayed: 0  [0201_adc]  (hidden comment: CRCW02010000Z0ED)
U13  LMH5401IRMSR  [RMS0014A]
U14  LMH6401IRMZR  [RMZ0016A]
U15  OPA376AIDCKT  [DCK0005A_N]
U62  BAL-0006SMG  [Marki_BAL-0006SMG]  (value not drawn)
U71  XLF-192+  [DQ1225]
U72  XLF-192+  [DQ1225]

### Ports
BLMH4_SCS (in), BLMH_CLK (in), BLMH_SDI (in), BLMH_SDO (out), IN4_N (in), IN4_P (in), Vcmo4 (out), VIN4_N (out), VIN4_P (out)

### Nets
AGND4: C195.2 C196.1 C197.1 C198.1 C199.1 C200.2 C201.2 C202.2 C203.2 C204.2 C206.2 C209.2 C211.2 C212.2 C213.2 C214.2 C215.1 C216.1 C217.1 C218.1 C219.1 C221.2 C222.2 J74.2 J74.3 J74.4 J74.5 J80.2 J80.3 J80.4 J81.2 J81.3 J81.4 L81.1(GND) L81.3(GND) L81.4(GND) L81.6(GND) L82.1(GND) L82.3(GND) L82.4(GND) L82.6(GND) LF7.2(GND) LF7.5(GND) LF8.2(GND) LF8.5(GND) R125.1 R126.1 R577.1 R582.1 R585.1 U13.11(GND) U13.14(GND) U14.9(GND) U14.12(GND) U71.1(GND) U71.3(GND) U71.4(NC) U71.5(NC) U71.6(NC) U71.7(GND) U71.9(GND) U71.10(NC) U71.11(NC) U71.12(NC) U71.13(PAD) U72.1(GND) U72.3(GND) U72.4(NC) U72.5(NC) U72.6(NC) U72.7(GND) U72.9(GND) U72.10(NC) U72.11(NC) U72.12(NC) U72.13(PAD)  [project net AGND]
VA3p75_LMH5401_4: C197.2 C201.1 C212.1 C216.2 C223.1(+) C225.1 C226.1 J84.2 R106.2 R110.2 R124.1 U13.1(VS+) U13.10(VS+)
VA3p75_LMH6401_4: C199.2 C203.1 C214.1 C218.2 C219.2 C224.1(+) C227.1 C228.1 J83.2 R583.2 U14.8(VCC) U14.13(VCC) U15.5(V+)
VA_n1p25_LMH5401_4: C196.2 C200.1 C211.1 C215.2 C223.2(-) C225.2 C226.2 R108.1 R580.2 R581.2 U13.3(VS-) U13.8(VS-)
VA_n1p25_LMH6401_4: C198.2 C202.1 C213.1 C217.2 C224.2(-) C227.2 C228.2 R584.1 U14.5(VEE) U14.16(VEE) U15.2(V-)
BLMH4_SCS: U14.15(~{CS}) ; port BLMH4_SCS
BLMH_CLK: U14.14(CLK) ; port BLMH_CLK
BLMH_SDI: U14.1(SDI) ; port BLMH_SDI
BLMH_SDO: U14.4(SDO) ; port BLMH_SDO
F_IN4N: LF8.3(OUT) R222.2 R674.1 R676.1
F_IN4P: LF7.3(OUT) R215.2 R671.1 R672.1
F_OUT4N: R610.1 R675.1 R677.2
F_OUT4P: R609.1 R670.1 R673.2
IN4_N: C207.1 C505.2 J80.1 R113.1 ; port IN4_N
IN4_P: C208.1 C506.1 C507.1 J81.1 R117.1 ; port IN4_P
Vcmo4: C222.1 R129.1 R583.1 R584.2 R585.2 U15.1(IN+) ; port Vcmo4
Vcmo_LMH5401_4: C220.1 R107.2 R128.1 R129.2 U15.4(OUT)
VIN4_N: R579.2 R610.2 ; port VIN4_N
VIN4_P: R578.2 R609.2 ; port VIN4_P
NetC7X_1: C7X.1 C204.1 L13.1 R116.1
NetC7X_2: C7X.2 C205.1 L13.2 L14.1
NetC8X_1: C8X.1 C209.1 L15.1 R120.1
NetC8X_2: C8X.2 C210.1 L15.2 L16.1
NetC195_1: C195.1 R106.1 R107.1 R108.2 R577.2 U13.2(CM)
NetC205_2: C205.2 C210.2
NetC206_1: C206.1 R112.1 R122.1 R127.2
NetC207_2: C207.2 R125.2
NetC208_2: C208.2 R126.2
NetC220_2: C220.2 R127.1 U15.3(IN-)
NetC221_1: C221.1 R128.2 U14.7(VOCM)
NetC505_1: C505.1 R110.1 R111.1 R113.2 R580.1 U13.5(IN-)
NetC506_2: C506.2 R117.2 R121.1 R124.2 R581.1 U13.6(IN+)
NetC507_2: C507.2 R582.2
NetJ74_1: J74.1 U62.1(IN)
NetJ83_1: J83.1 U14.6(PD)
NetJ84_1: J84.1 U13.9(PD)
NetL14_2: L14.2 R109.1 R112.2
NetL16_2: L16.2 R122.2 R123.1
NetL81_2: L81.2(IN) R109.2 R644.1
NetL81_5: L81.5(OUT) LF7.1(IN) R215.1 R644.2
NetL82_2: L82.2(IN) R123.2 R645.1
NetL82_5: L82.5(OUT) LF8.1(IN) R222.1 R645.2
NetR111_2: R111.2 U13.4(FB+)
NetR114_1: R114.1 U13.13(OUT+)
NetR114_2: R114.2 R115.2
NetR115_1: R115.1 U14.2(INP)
NetR116_2: R116.2 U14.11(OUTP)
NetR118_1: R118.1 U13.12(OUT-)
NetR118_2: R118.2 R119.2
NetR119_1: R119.1 U14.3(INM)
NetR120_2: R120.2 U14.10(OUTM)
NetR121_2: R121.2 U13.7(FB-)
NetR578_1: R578.1 U62.3(O2)
NetR579_1: R579.1 U62.2(O1)
NetR670_2: R670.2 U71.8(RF-OUT)
NetR671_2: R671.2 U71.2(RF-IN)
NetR672_2: R672.2 R673.1
NetR674_2: R674.2 U72.2(RF-IN)
NetR675_2: R675.2 U72.8(RF-OUT)
NetR676_2: R676.2 R677.1

Not connected (* = marked no-connect by the designer): LF7 4(NC) 6(NC); LF8 4(NC) 6(NC)

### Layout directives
differential pair: IN4_N, IN4_P, NetR114_1, NetR115_1, NetR118_1, NetR119_1

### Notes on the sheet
- ANALOG INPUT CH-4
- (near C7X) *
- (near C507) 0E
- (near C207) 0E
- (near C208) 0E
- *
- Note:
  1)  Replace capacitor ( C507, C207, C208)  with 0E resistor for DC coupling
  50 E  impedance
  2) * Added onboard but not in the layout

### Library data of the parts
C7X C8X = 885012006086: as C5X on sheet TIDA-01022-E2_ADC ANALOG INP CH3
C195 C206-C208 C221 C507 = GRM155R71E103KA01D: as C161 on sheet TIDA-01022-E2_ADC ANALOG INP CH3
C196-C199 C215-C218 = LLL185R71E103MA01L: as C162-C165 on sheet TIDA-01022-E2_ADC ANALOG INP CH3
C200-C203 C211-C214 = LLL185R71H222MA01L: as C166-C169 on sheet TIDA-01022-E2_ADC ANALOG INP CH3
C204 C209 = GRM1555C1H1R0CA01D: as C170 on sheet TIDA-01022-E2_ADC ANALOG INP CH3
C205 C210 = GRM1555C1H1R2BA01D: as C171 on sheet TIDA-01022-E2_ADC ANALOG INP CH3
C219 C222 C225-C228 = C1005X5R1A104K050BA: as C185 on sheet TIDA-01022-E2_ADC ANALOG INP CH3
C220 = C1608X5R1A105K080AC: as C186 on sheet TIDA-01022-E2_ADC ANALOG INP CH3
C223 C224 = TPSA106K010R0900: as C189 on sheet TIDA-01022-E2_ADC ANALOG INP CH3
C505 C506 = GRM155R71C104JA88D: as C502 on sheet TIDA-01022-E2_ADC ANALOG INP CH3
J74 = 142-0701-201: as J29 on sheet TIDA-01022-E2_ADC ANALOG INP CH3
J80 J81 = 142-0771-831: as J76 on sheet TIDA-01022-E2_ADC ANALOG INP CH3
J83 J84 = TSW-102-07-G-S: as J79 on sheet TIDA-01022-E2_ADC ANALOG INP CH3
L13 L15 = LQW18AN5N6D10D: as L9 on sheet TIDA-01022-E2_ADC ANALOG INP CH3
L14 L16 = 0603HC-3N9XJLU: as L10 on sheet TIDA-01022-E2_ADC ANALOG INP CH3
L81 L82 = WE-LPF, 748112024: as L79 on sheet TIDA-01022-E2_ADC ANALOG INP CH3
LF7 LF8 = LFL182G45TC3B746: as LF5 on sheet TIDA-01022-E2_ADC ANALOG INP CH3
R106 R108 R577 R583-R585 = CRCW04022K00FKED: as R82 on sheet TIDA-01022-E2_ADC ANALOG INP CH3
R107 R114 R115 R118 R119 R128 R129 R215 R222 R644 R645 = CRCW04020000Z0ED: as R83 on sheet TIDA-01022-E2_ADC ANALOG INP CH3
R109 R123 = CRCW04024R99FKED: as R85 on sheet TIDA-01022-E2_ADC ANALOG INP CH3
R110 R124 R580 R581 = ERJ-2RKF1001X: as R86 on sheet TIDA-01022-E2_ADC ANALOG INP CH3
R111 R121 = CRCW0402127RFKED: as R87 on sheet TIDA-01022-E2_ADC ANALOG INP CH3
R112 R122 = CRCW04021K21FKED: as R88 on sheet TIDA-01022-E2_ADC ANALOG INP CH3
R113 R117 = CRCW040222R6FKED: as R89 on sheet TIDA-01022-E2_ADC ANALOG INP CH3
R116 R120 = CRCW040240R2FKED: as R92 on sheet TIDA-01022-E2_ADC ANALOG INP CH3
R125 R126 = CRCW0402365RFKED: as R101 on sheet TIDA-01022-E2_ADC ANALOG INP CH3
R127 = CRCW040210K0FKED: as R103 on sheet TIDA-01022-E2_ADC ANALOG INP CH3
R578 R579 R609 R610 R670-R677 = CRCW02010000Z0ED: as R569 on sheet TIDA-01022-E2_ADC ANALOG INP CH3
R582 = FC0402E50R0BTBST1: as R573 on sheet TIDA-01022-E2_ADC ANALOG INP CH3
U13 = LMH5401IRMSR: as U10 on sheet TIDA-01022-E2_ADC ANALOG INP CH3
U14 = LMH6401IRMZR: as U11 on sheet TIDA-01022-E2_ADC ANALOG INP CH3
U15 = OPA376AIDCKT: as U12 on sheet TIDA-01022-E2_ADC ANALOG INP CH3
U62 = BAL-0006SMG: as U61 on sheet TIDA-01022-E2_ADC ANALOG INP CH3
U71 U72 = CMP-0077784-1: as U69 on sheet TIDA-01022-E2_ADC ANALOG INP CH3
